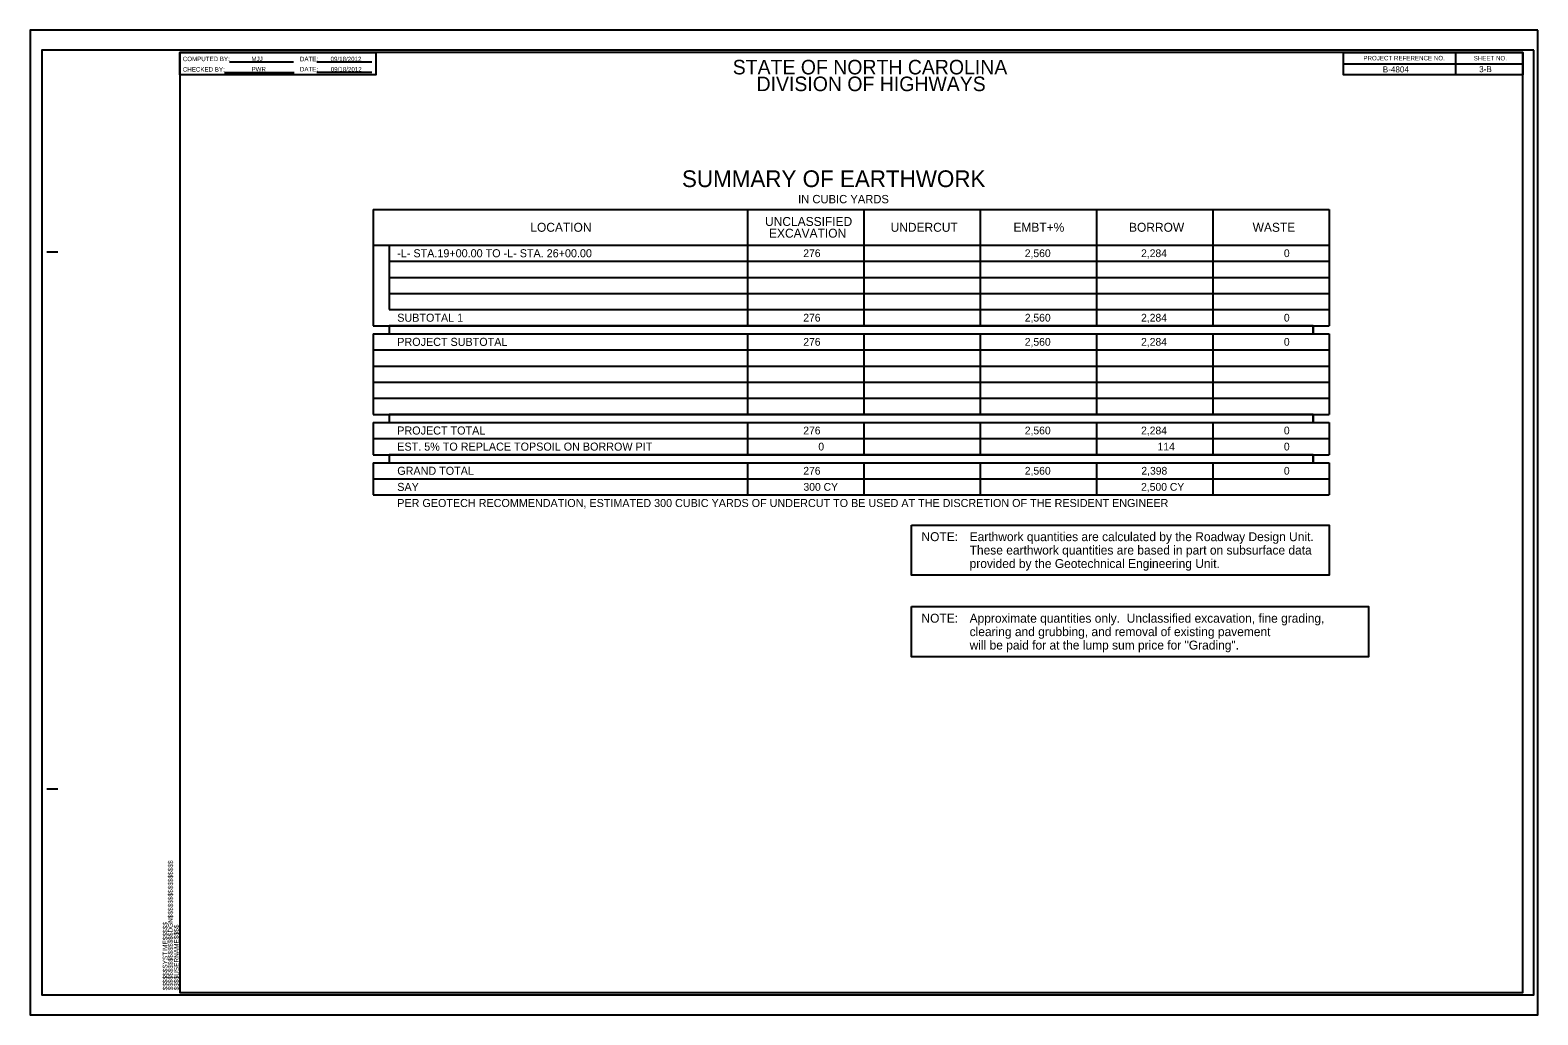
# Model space of a CAD drawing. Extents: x 559923 to 578088, y -61429 to -54466.
# Drawn here: x 574430 to 576114, y -56866 to -55766 of the extents above; entities that cross this region are included whole.
import ezdxf

# ---------------------------------------------------------------- set-up
doc = ezdxf.new("R2010")
doc.units = 0
for name, color, linetype in [('Prop DSN Text', 7, 'Continuous'), ('Prop Shade Medium', 7, 'Continuous'), ('Sheet Cutting Line CELL', 7, 'Continuous'), ('Sheet Data Field CELL', 7, 'Continuous'), ('Sheet Plot Border Inside CELL', 7, 'Continuous'), ('Sheet Plot Border Outside CELL', 7, 'Continuous'), ('Sheet Summary CELL', 7, 'Continuous'), ('Sheet Summary Earthwork CELL', 7, 'Continuous')]:
    doc.layers.add(name, color=color, linetype=linetype)

msp = doc.modelspace()

# ---------------------------------------------------------------- linework, layer by layer
at = {"layer": 'Prop DSN Text'}
for points in [[(575414, -56318.5), (575880.6, -56318.5), (575880.6, -56374.5), (575414, -56374.5)], [(575414, -56409.6), (575924.5, -56409.6), (575924.5, -56465.6), (575414, -56465.6)]]:
    msp.add_lwpolyline(points, close=True, dxfattribs=at)
at = {"layer": 'Prop Shade Medium'}
for points in [[(574830.6, -56104.9), (575862.6, -56104.9), (575862.6, -56095.9), (574830.6, -56095.9)], [(574830.6, -56203.9), (575862.6, -56203.9), (575862.6, -56194.9), (574830.6, -56194.9)], [(574830.6, -56248.9), (575862.6, -56248.9), (575862.6, -56239.9), (574830.6, -56239.9)]]:
    msp.add_lwpolyline(points, close=True, dxfattribs=at)
at = {"layer": 'Sheet Cutting Line CELL'}
for p, q in [((576113.6, -55765.7), (574429.6, -55765.7)), ((574429.6, -55765.7), (574429.6, -56865.7)), ((574429.6, -56865.7), (576113.6, -56865.7))]:
    msp.add_line(p, q, dxfattribs=at)
at = {"layer": 'Sheet Plot Border Inside CELL'}
msp.add_lwpolyline([(576109.1, -55788.1), (574442.6, -55788.1), (574442.6, -56843.2), (576109.1, -56843.2)], close=True, dxfattribs=at)
at = {"layer": 'Sheet Plot Border Outside CELL'}
msp.add_lwpolyline([(576113.6, -55765.7), (574429.6, -55765.7), (574429.6, -56865.7), (576113.6, -56865.7)], close=True, dxfattribs=at)
at = {"layer": 'Sheet Summary CELL'}
for p, q in [((574812.6, -55965.9), (575880.6, -55965.9)), ((574812.6, -55965.9), (574812.6, -56095.9)), ((575230.6, -55965.9), (575230.6, -56095.9)), ((575360.6, -55965.9), (575360.6, -56095.9)), ((575490.6, -55965.9), (575490.6, -56095.9)), ((575620.6, -55965.9), (575620.6, -56095.9)), ((575750.6, -55965.9), (575750.6, -56095.9)), ((575880.6, -55965.9), (575880.6, -56095.9)), ((574812.6, -56005.9), (575880.6, -56005.9)), ((574830.6, -56005.9), (574830.6, -56077.9)), ((574830.6, -56023.9), (575880.6, -56023.9)), ((574830.6, -56041.9), (575880.6, -56041.9)), ((574830.6, -56059.9), (575880.6, -56059.9)), ((574830.6, -56077.9), (575880.6, -56077.9)), ((574812.6, -56095.9), (575880.6, -56095.9)), ((574812.6, -56104.9), (575880.6, -56104.9)), ((574812.6, -56104.9), (574812.6, -56194.9)), ((574830.6, -56095.9), (574830.6, -56104.9)), ((575230.6, -56104.9), (575230.6, -56194.9)), ((575360.6, -56104.9), (575360.6, -56194.9)), ((575490.6, -56104.9), (575490.6, -56194.9)), ((575620.6, -56104.9), (575620.6, -56194.9)), ((575750.6, -56104.9), (575750.6, -56194.9)), ((575862.6, -56095.9), (575862.6, -56104.9)), ((575880.6, -56104.9), (575880.6, -56194.9)), ((574812.6, -56122.9), (575880.6, -56122.9)), ((574812.6, -56140.9), (575880.6, -56140.9)), ((574812.6, -56158.9), (575880.6, -56158.9)), ((574812.6, -56176.9), (575880.6, -56176.9)), ((574812.6, -56194.9), (575880.6, -56194.9)), ((574830.6, -56194.9), (574830.6, -56203.9)), ((575862.6, -56194.9), (575862.6, -56203.9)), ((574812.6, -56203.9), (574812.6, -56239.9)), ((574812.6, -56203.9), (575880.6, -56203.9)), ((575230.6, -56203.9), (575230.6, -56239.9)), ((575360.6, -56203.9), (575360.6, -56239.9)), ((575490.6, -56203.9), (575490.6, -56239.9)), ((575620.6, -56203.9), (575620.6, -56239.9)), ((575750.6, -56203.9), (575750.6, -56239.9)), ((575880.6, -56203.9), (575880.6, -56239.9)), ((574812.6, -56221.9), (575880.6, -56221.9)), ((574812.6, -56239.9), (575880.6, -56239.9)), ((574830.6, -56239.9), (574830.6, -56248.9)), ((575862.6, -56239.9), (575862.6, -56248.9)), ((574812.6, -56248.9), (574812.6, -56284.9)), ((574812.6, -56248.9), (575880.6, -56248.9)), ((575230.6, -56248.9), (575230.6, -56284.9)), ((575360.6, -56248.9), (575360.6, -56284.9)), ((575490.6, -56248.9), (575490.6, -56284.9)), ((575620.6, -56248.9), (575620.6, -56284.9)), ((575750.6, -56248.9), (575750.6, -56284.9)), ((575880.6, -56248.9), (575880.6, -56284.9)), ((574812.6, -56266.9), (575880.6, -56266.9)), ((574812.6, -56284.9), (575880.6, -56284.9))]:
    msp.add_line(p, q, dxfattribs=at)
at = {"layer": 'Sheet Summary Earthwork CELL'}
for p, q in [((576021.6, -55790.7), (576021.6, -55815.7)), ((574652.2, -55801.1), (574723.8, -55801.1)), ((574749.6, -55801.2), (574811, -55801.2)), ((575896.5, -55803.2), (576096.6, -55803.2)), ((574646.8, -55812.8), (574724.5, -55812.8)), ((574749.7, -55812.7), (574811.1, -55812.7)), ((574448.1, -56013.2), (574460.6, -56013.2)), ((574448.1, -56613.2), (574460.6, -56613.2)), ((574596.6, -56840.7), (574596.6, -56840.7)), ((574596.6, -56840.7), (574596.6, -56840.7)), ((574596.6, -56840.7), (574596.6, -56840.7)), ((574596.6, -56840.7), (574596.6, -56840.7)), ((574596.6, -56840.7), (574596.6, -56840.7)), ((574596.6, -56840.7), (574596.6, -56840.7)), ((574596.6, -56840.7), (574596.6, -56840.7)), ((574596.6, -56840.7), (574596.6, -56840.7)), ((574596.6, -56840.7), (574596.6, -56840.7))]:
    msp.add_line(p, q, dxfattribs=at)
for points in [[(576096.6, -55790.7), (574596.6, -55790.7), (574596.6, -56840.7), (576096.6, -56840.7)], [(574596.6, -55790.7), (574815.6, -55790.7), (574815.6, -55815.7), (574596.6, -55815.7)], [(575896.5, -55790.7), (576096.6, -55790.7), (576096.6, -55815.7), (575896.5, -55815.7)]]:
    msp.add_lwpolyline(points, close=True, dxfattribs=at)
msp.add_lwpolyline([(574634.1, -56840.7), (574634.1, -56840.7)], dxfattribs=at)

# ---------------------------------------------------------------- texts
at = {"layer": 'Prop DSN Text'}
for s, height, p in [('STATE OF NORTH CAROLINA', 16.25, (575214.3, -55815.1)), ('DIVISION OF HIGHWAYS', 16.25, (575240.9, -55833.8)), ('SUMMARY OF EARTHWORK', 18.7, (575157.6, -55941)), ('IN CUBIC YARDS', 9.349, (575287.3, -55959.1)), ('UNCLASSIFIED', 10, (575250.4, -55984.4)), ('LOCATION', 10, (574988.2, -55990.9)), ('EXCAVATION', 10, (575254.8, -55997.5)), ('UNDERCUT', 10, (575390.6, -55990.9)), ('EMBT+%', 10, (575527.8, -55990.9)), ('BORROW', 10, (575656.9, -55990.9)), ('WASTE', 10, (575795, -55990.9)), ('-L- STA.19+00.00 TO -L- STA. 26+00.00', 9, (574839.6, -56019.4)), ('276', 8.64, (575293.1, -56019.2)), ('2,560', 8.64, (575540.5, -56019.2)), ('2,284', 8.64, (575670.4, -56019.2)), ('0', 8.64, (575829.9, -56019.2)), ('SUBTOTAL 1', 9, (574839.6, -56091.4)), ('276', 8.64, (575293.1, -56091.2)), ('2,560', 8.64, (575540.5, -56091.2)), ('2,284', 8.64, (575670.4, -56091.2)), ('0', 8.64, (575829.9, -56091.2)), ('PROJECT SUBTOTAL', 9, (574839.6, -56118.4)), ('276', 8.64, (575293.1, -56118.2)), ('2,560', 8.64, (575540.5, -56118.2)), ('2,284', 8.64, (575670.4, -56118.2)), ('0', 8.64, (575829.9, -56118.2)), ('PROJECT TOTAL', 9, (574839.6, -56217.4)), ('276', 8.64, (575293.1, -56217.2)), ('2,560', 8.64, (575540.5, -56217.2)), ('2,284', 8.64, (575670.4, -56217.2)), ('0', 8.64, (575829.9, -56217.2)), ('EST. 5% TO REPLACE TOPSOIL ON BORROW PIT', 9, (574839.6, -56235.4)), ('0', 8.64, (575309.9, -56235.2)), ('114', 8.64, (575688.8, -56235.2)), ('0', 8.64, (575829.9, -56235.2)), ('GRAND TOTAL', 9, (574839.6, -56262.4)), ('276', 8.64, (575293.1, -56262.2)), ('2,560', 8.64, (575540.5, -56262.2)), ('2,398', 8.64, (575670.7, -56262.2)), ('0', 8.64, (575829.9, -56262.2)), ('SAY', 9, (574839.6, -56280.4)), ('300 CY', 8.64, (575293.3, -56280.2)), ('2,500 CY', 8.64, (575670.4, -56280.2)), ('PER GEOTECH RECOMMENDATION, ESTIMATED 300 CUBIC YARDS OF UNDERCUT TO BE USED AT THE DISCRETION OF THE RESIDENT ENGINEER', 9, (574839.6, -56298.4)), ('NOTE:', 10, (575425.1, -56336.5)), ('Earthwork quantities are calculated by the Roadway Design Unit. ', 10, (575478.9, -56336.5)), ('These earthwork quantities are based in part on subsurface data ', 10, (575478.9, -56351.5)), ('provided by the Geotechnical Engineering Unit.', 10, (575478.9, -56366.5)), ('NOTE:', 10, (575425.1, -56427.6)), ('Approximate quantities only.  Unclassified excavation, fine grading,', 10, (575478.9, -56427.6)), ('will be paid for at the lump sum price for "Grading".', 10, (575478.9, -56457.6)), ('clearing and grubbing, and removal of existing pavement', 10, (575478.9, -56442.6))]:
    msp.add_text(s, height=height, dxfattribs=at).set_placement(p)
at = {"layer": 'Sheet Data Field CELL'}
for s, height, p in [('MJJ', 5, (574676.7, -55800.3)), ('PWR', 5, (574676.8, -55811.8)), ('09/18/2012', 5, (574765.1, -55800.4)), ('09/18/2012', 5, (574765.3, -55811.9)), ('B-4804', 6.75, (575940.4, -55812.9)), ('3-B', 6.75, (576048, -55812.6))]:
    msp.add_text(s, height=height, dxfattribs=at).set_placement(p)
at = {"layer": 'Sheet Summary Earthwork CELL'}
for s, p in [('COMPUTED BY:', (574600, -55800.3)), ('CHECKED BY:', (574600.1, -55812)), ('DATE:', (574730.9, -55800.4)), ('DATE:', (574730.9, -55811.8)), ('PROJECT REFERENCE NO.', (575918.7, -55799.4)), ('SHEET NO.', (576041.9, -55799.5))]:
    msp.add_text(s, height=5, dxfattribs=at).set_placement(p)
for s, p in [('$$$$$$$$$$$$$$$$DGN$$$$$$$$$$$$$$$$', (574588.9, -56838.3)), ('$$$$$$SYSTIME$$$$$', (574582.9, -56838.3)), ('$$$$USERNAME$$$$', (574595.5, -56838.3))]:
    msp.add_text(s, height=5.25, rotation=90, dxfattribs=at).set_placement(p)

doc.saveas('drawing.dxf')
